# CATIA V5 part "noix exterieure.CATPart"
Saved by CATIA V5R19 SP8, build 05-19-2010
Part number: noix exterieure
Revision: ANY
Definition: UNKNOWN
Nomenclature: noix exterieure
Source: Unknown
Bounding box of the stored display mesh (mm): x 0 to 12.5, y -10 to 10, z -10 to 10
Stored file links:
  D:\Documents\1_Travail\1 - ac-limoges.fr\ac-limoges.fr\Emmanuel Maynard - STI2D_Turgot\2 -2I2D\2_SEQUENCE_Serrure_Biométrique\5-Spé_ITEC\Serrure_Bio_Eleve\noix exterieure.CATPart
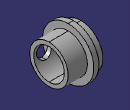
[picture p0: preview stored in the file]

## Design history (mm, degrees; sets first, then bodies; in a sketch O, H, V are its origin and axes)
Body1 "Enlèv. mat.-Extru.3" (main body)
  Solid1: solid without history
